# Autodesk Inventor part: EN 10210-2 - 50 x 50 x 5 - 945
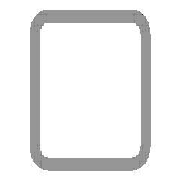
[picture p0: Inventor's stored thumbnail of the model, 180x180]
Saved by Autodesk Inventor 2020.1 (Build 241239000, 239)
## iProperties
_CCFamilyMember: 16
_CCFamilyDisplayName: DIN EN 10210-2 (USAS B17.1 quadratisch) - Rohrleitung — In Klammern angegebene Größen wurden aufgehoben
_FrameMemberDoc: Frame Member File
_Version: 15.0.0
_GetPNFromCC: 1
IsCustomPart: 1
Created: 2019-10
Part Number: EN 10210-2 - 50 x 50 x 5 - 945
Material: Stahl, weich
Description: Rohrleitung
Document SubType Name: Modeling
Standard: DIN
Designer: lutzd
Standard Revision: 2006-07
Standards Organization: DIN
Language: de-DE
Size Designation: 50 x 50 x 5
Categories: <MemberInstance><Categories><Category DisplayName="Profile" InternalName="089c4875-fa83-4c05-b084-43b9cc11f5ed" Mnemonic="GRDR"><CategoryParameter DisplayName="
Stock Number: 50 x 50 x 5
Mass: 6477.43 g
Surface Area: 3216.66 cm^2
Volume: 825.15 cm^3
Density: 7.85 g/cm^3
Appearance: Halbpoliert
G_L: 945,000 mm
G_W: 50,000 mm
G_H: 50,000 mm
Dimensions: 50x50x945 mm
Mass: 6,477 kg
DocNumber: ADSK-014100
Folder: .
+7C0F244C-9007-407E-94B7-58167DA6CB54+SCHNITTDETAIL1: Schnittwinkel 90,00 grd
Title: Profil-Bauteil
Author: lutzd
Revision Number: -
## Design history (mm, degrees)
node "Startebene"
node "Endebene"
sketch "Skizze"
  geometry: L1 (-25, -17.5)-(-25, 17.5); L2 (-17.5, 25)-(17.5, 25); L3 (25, 17.5)-(25, -17.5); L4 (17.5, -25)-(-17.5, -25); L5 (-15, 20)-(15, 20); L6 (20, 15)-(20, -15); L7 (15, -20)-(-15, -20); L8 (-20, -15)-(-20, 15); L9 (0, 37.175)-(0, -37.175) reference; L10 (-37.175, 0)-(37.175, 0) reference; A1 r 7.5 centre (-17.5, -17.5) between (-25, -17.5) and (-17.5, -25); A2 r 7.5 centre (-17.5, 17.5) between (-17.5, 25) and (-25, 17.5); A3 r 7.5 centre (17.5, 17.5) between (25, 17.5) and (17.5, 25); A4 r 7.5 centre (17.5, -17.5) between (17.5, -25) and (25, -17.5); A5 r 5 centre (-15, -15) between (-20, -15) and (-15, -20); A6 r 5 centre (-15, 15) between (-15, 20) and (-20, 15); A7 r 5 centre (15, 15) between (20, 15) and (15, 20); A8 r 5 centre (15, -15) between (15, -20) and (20, -15)
  constraints: 16 end point, 16 point on circle, 16 tangent, 8 centre point, 6 equal radius, 4 parallel, 2 perpendicular, 2 other
  dimensions: "d7" = 7.5 radius of A1 (= G_IR); "d10" = 50 distance between parallel lines of L2 L4 (= G_H); "d11" = 50 distance between parallel lines of L1 L3 (= G_W); "d12" = 5 distance between parallel lines of L3 L6 (= G_T); "d15" = 25 distance between parallel lines of L2 L10 (= 0.5 x d10); "d16" = 25 distance between parallel lines of L9 L3 (= 0.5 x d11); "d19" = 5 radius of A5 (= G_T); "d20" = 5 distance between parallel lines of L4 L7 (= G_T)
extrude "Körper" new body sketch "Skizze" stored distance "d3" = 945 (= G_L); taper "d4" = 0 deg
node "Driven Length"
  sketch "Sketch3"
    geometry: L1 (0, 0)-(10, 0) reference
    constraints: 2 end point, 1 horizontal
  workplane "Work Plane3"
  sketch "Sketch4"
    geometry: L1 (-2, 70)-(12, 70) reference; L2 (-2, 1015)-(12, 1015) reference
    dimensions: "d18" = 945 distance between parallel lines of L1 L2 (derived)
workplane "Arbeitsebene4"
feature "Trennen1"
body "Solid1"
other parameters: "G_W" = 50 [user parameter; used in 1 equation term], "G_H" = 50 [user parameter; used in 1 equation term], "G_T" = 5 [user parameter; used in 3 equation terms], "G_IR" = 7.5 [user parameter; used in 1 equation term], "G_L" = 945 (= d18) [user parameter; used in 1 equation term], "G_OFFSET_END" = -35 [user parameter; used in 1 equation term], "d14" = 1015 (= G_OFFSET_END + B_L), "d17" = 90 deg
